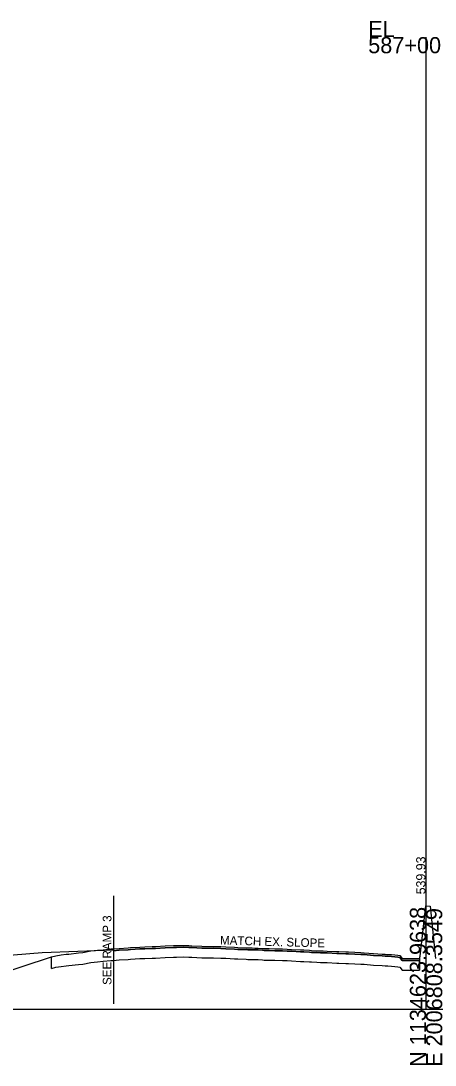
# Model space of a CAD drawing. Extents: x -201 to 2007062, y -213 to 1139737.
# Drawn here: x 1180 to 1251.6, y 2490.3 to 2671 of the extents above; entities that cross this region are included whole.
import ezdxf

# ---------------------------------------------------------------- set-up
doc = ezdxf.new("R2010")
doc.units = 0
for name, color, linetype in [('RD_DTM_Design_FG', 7, 'Continuous'), ('RD_GPK_XS_Cell', 7, 'Continuous'), ('RD_XS_ExGround', 7, 'Continuous'), ('RD_XS_ExPaveRet', 7, 'Continuous'), ('RD_XS_PaveOvlay', 7, 'Continuous'), ('RD_XS_SideStreet', 7, 'Continuous'), ('RD_XS_TX_Elev_EX', 7, 'Continuous'), ('RD_XS_TX_Slope', 7, 'Continuous')]:
    doc.layers.add(name, color=color, linetype=linetype)

msp = doc.modelspace()

# ---------------------------------------------------------------- linework, layer by layer
at = {"layer": 'RD_DTM_Design_FG'}
msp.add_lwpolyline([(1102.81, 2555.58), (1109.38, 2549), (1127.28, 2531.09), (1142.71, 2515.65), (1155.64, 2502.71), (1163.28, 2505.25), (1173.65, 2508.68), (1174.62, 2508.84), (1177.65, 2509.32), (1178.72, 2509.4), (1183.66, 2509.79), (1189.83, 2510.02), (1196, 2510.26)], dxfattribs=at)
at = {"layer": 'RD_GPK_XS_Cell'}
for p, q in [((1250, 2500), (1250, 2668.19)), ((1000, 2500), (1250, 2500)), ((1250, 2500), (1500, 2500))]:
    msp.add_line(p, q, dxfattribs=at)
at = {"layer": 'RD_XS_ExGround'}
msp.add_lwpolyline([(1174.91, 2505.63), (1185.26, 2509.03), (1186, 2509.24), (1186.93, 2509.37), (1187.79, 2509.48), (1188.27, 2509.53), (1189.91, 2509.73), (1190.7, 2509.79), (1192.05, 2510.06), (1193.21, 2510.18), (1194.22, 2510.28), (1195.54, 2510.41), (1195.86, 2510.42), (1196.97, 2510.51), (1198.54, 2510.61), (1198.92, 2510.63), (1200.52, 2510.73), (1201.4, 2510.76), (1202.64, 2510.82), (1203.24, 2510.84), (1204.92, 2510.93), (1206.37, 2511), (1206.89, 2511.01), (1208.02, 2511.03), (1209.01, 2510.99), (1209.51, 2510.97), (1211.25, 2510.89), (1213.25, 2510.85), (1214.53, 2510.81), (1215.37, 2510.79), (1216.91, 2510.7), (1217.49, 2510.67), (1218.91, 2510.62), (1219.21, 2510.61), (1219.62, 2510.59), (1219.92, 2510.58), (1220.39, 2510.57), (1221.01, 2510.56), (1221.74, 2510.51), (1222.04, 2510.49), (1222.91, 2510.47), (1223.86, 2510.44), (1225.18, 2510.41), (1225.98, 2510.38), (1226.74, 2510.33), (1228.31, 2510.26), (1228.9, 2510.23), (1229.88, 2510.17), (1230.22, 2510.15), (1231.11, 2510.11), (1231.76, 2510.09), (1232.22, 2510.06), (1232.89, 2510.05), (1234.58, 2509.96), (1234.9, 2509.95), (1236.15, 2509.91), (1236.59, 2509.89), (1237.71, 2509.85), (1238.71, 2509.79), (1239.28, 2509.75), (1240.9, 2509.62), (1242.41, 2509.53), (1242.95, 2509.49), (1243.37, 2509.46), (1244.01, 2509.44), (1244.63, 2509.38), (1245.1, 2509.31), (1245.45, 2509.25), (1245.85, 2508.73), (1248.3, 2508.76), (1248.88, 2508.74), (1249, 2509.18), (1249.98, 2517.87), (1250.74, 2517.83), (1251.64, 2508.76)], dxfattribs=at)
at = {"layer": 'RD_XS_ExPaveRet'}
for p, q in [((1196, 2510.1), (1196, 2508.43)), ((1185.26, 2507.03), (1185.26, 2509.03)), ((1190.7, 2507.79), (1192.05, 2508.06)), ((1192.05, 2508.06), (1193.21, 2508.18)), ((1193.21, 2508.18), (1194.22, 2508.28)), ((1194.22, 2508.28), (1195.54, 2508.41)), ((1195.54, 2508.41), (1195.86, 2508.42)), ((1195.86, 2508.42), (1196.97, 2508.51)), ((1196, 2508.43), (1196.97, 2508.51)), ((1196.97, 2508.51), (1198.54, 2508.61)), ((1196.97, 2508.51), (1198.54, 2508.61)), ((1198.54, 2508.61), (1198.92, 2508.63)), ((1198.54, 2508.61), (1198.92, 2508.63)), ((1198.92, 2508.63), (1200.52, 2508.73)), ((1198.92, 2508.63), (1200.52, 2508.73)), ((1200.52, 2508.73), (1201.4, 2508.76)), ((1200.52, 2508.73), (1201.4, 2508.76)), ((1201.4, 2508.76), (1202.64, 2508.82)), ((1201.4, 2508.76), (1202.64, 2508.82)), ((1202.64, 2508.82), (1203.24, 2508.84)), ((1202.64, 2508.82), (1203.24, 2508.84)), ((1203.24, 2508.84), (1204.92, 2508.93)), ((1203.24, 2508.84), (1204.92, 2508.93)), ((1204.92, 2508.93), (1206.37, 2509)), ((1204.92, 2508.93), (1206.37, 2509)), ((1206.37, 2509), (1206.89, 2509.01)), ((1206.37, 2509), (1206.89, 2509.01)), ((1206.89, 2509.01), (1208.02, 2509.03)), ((1206.89, 2509.01), (1208.02, 2509.03)), ((1208.02, 2509.03), (1209.01, 2508.99)), ((1208.02, 2509.03), (1209.01, 2508.99)), ((1209.01, 2508.99), (1209.51, 2508.97)), ((1209.01, 2508.99), (1209.51, 2508.97)), ((1209.51, 2508.97), (1211.25, 2508.89)), ((1209.51, 2508.97), (1211.25, 2508.89)), ((1211.25, 2508.89), (1213.25, 2508.85)), ((1211.25, 2508.89), (1213.25, 2508.85)), ((1213.25, 2508.85), (1214.53, 2508.81)), ((1213.25, 2508.85), (1214.53, 2508.81)), ((1214.53, 2508.81), (1215.37, 2508.79)), ((1214.53, 2508.81), (1215.37, 2508.79)), ((1215.37, 2508.79), (1216.91, 2508.7)), ((1215.37, 2508.79), (1216.91, 2508.7)), ((1216.91, 2508.7), (1217.49, 2508.67)), ((1216.91, 2508.7), (1217.49, 2508.67)), ((1217.49, 2508.67), (1218.91, 2508.62)), ((1217.49, 2508.67), (1218.91, 2508.62)), ((1218.91, 2508.62), (1219.21, 2508.61)), ((1218.91, 2508.62), (1219.21, 2508.61)), ((1219.21, 2508.61), (1219.62, 2508.59)), ((1219.21, 2508.61), (1219.62, 2508.59)), ((1219.62, 2508.59), (1219.92, 2508.58)), ((1219.62, 2508.59), (1219.92, 2508.58)), ((1219.92, 2508.58), (1220.39, 2508.57)), ((1219.92, 2508.58), (1220.39, 2508.57)), ((1220.39, 2508.57), (1221.01, 2508.56)), ((1220.39, 2508.57), (1221.01, 2508.56)), ((1221.01, 2508.56), (1221.74, 2508.51)), ((1221.01, 2508.56), (1221.74, 2508.51)), ((1221.74, 2508.51), (1222.04, 2508.49)), ((1221.74, 2508.51), (1222.04, 2508.49)), ((1222.04, 2508.49), (1222.91, 2508.47)), ((1222.04, 2508.49), (1222.91, 2508.47)), ((1222.91, 2508.47), (1223.86, 2508.44)), ((1222.91, 2508.47), (1223.86, 2508.44)), ((1223.86, 2508.44), (1225.18, 2508.41)), ((1223.86, 2508.44), (1225.18, 2508.41)), ((1225.18, 2508.41), (1225.98, 2508.38)), ((1225.18, 2508.41), (1225.98, 2508.38)), ((1225.98, 2508.38), (1226.74, 2508.33)), ((1225.98, 2508.38), (1226.74, 2508.33)), ((1226.74, 2508.33), (1228.31, 2508.26)), ((1226.74, 2508.33), (1228.31, 2508.26)), ((1228.31, 2508.26), (1228.9, 2508.23)), ((1228.31, 2508.26), (1228.9, 2508.23)), ((1228.9, 2508.23), (1229.88, 2508.17)), ((1228.9, 2508.23), (1229.88, 2508.17)), ((1229.88, 2508.17), (1230.22, 2508.15)), ((1229.88, 2508.17), (1230.22, 2508.15)), ((1230.22, 2508.15), (1231.11, 2508.11)), ((1230.22, 2508.15), (1231.11, 2508.11)), ((1231.11, 2508.11), (1231.76, 2508.09)), ((1231.11, 2508.11), (1231.76, 2508.09)), ((1231.76, 2508.09), (1232.22, 2508.06)), ((1231.76, 2508.09), (1232.22, 2508.06)), ((1232.22, 2508.06), (1232.89, 2508.05)), ((1232.22, 2508.06), (1232.89, 2508.05)), ((1232.89, 2508.05), (1234.58, 2507.96)), ((1232.89, 2508.05), (1234.58, 2507.96)), ((1234.58, 2507.96), (1234.9, 2507.95)), ((1234.58, 2507.96), (1234.9, 2507.95)), ((1234.9, 2507.95), (1236.15, 2507.91)), ((1234.9, 2507.95), (1236.15, 2507.91)), ((1236.15, 2507.91), (1236.59, 2507.89)), ((1236.15, 2507.91), (1236.59, 2507.89)), ((1236.59, 2507.89), (1237.71, 2507.85)), ((1236.59, 2507.89), (1237.71, 2507.85)), ((1248.88, 2508.74), (1248.88, 2506.74)), ((1248.88, 2506.74), (1248.88, 2508.41)), ((1185.26, 2507.03), (1186, 2507.24)), ((1186, 2507.24), (1186.93, 2507.37)), ((1186.93, 2507.37), (1187.79, 2507.48)), ((1187.79, 2507.48), (1188.27, 2507.53)), ((1188.27, 2507.53), (1189.91, 2507.73)), ((1189.91, 2507.73), (1190.7, 2507.79)), ((1237.71, 2507.85), (1238.71, 2507.79)), ((1237.71, 2507.85), (1238.71, 2507.79)), ((1238.71, 2507.79), (1239.28, 2507.75)), ((1238.71, 2507.79), (1239.28, 2507.75)), ((1239.28, 2507.75), (1240.9, 2507.62)), ((1239.28, 2507.75), (1240.9, 2507.62)), ((1240.9, 2507.62), (1242.41, 2507.53)), ((1240.9, 2507.62), (1242.41, 2507.53)), ((1242.41, 2507.53), (1242.95, 2507.49)), ((1242.41, 2507.53), (1242.95, 2507.49)), ((1242.95, 2507.49), (1243.37, 2507.46)), ((1242.95, 2507.49), (1243.37, 2507.46)), ((1243.37, 2507.46), (1244.01, 2507.44)), ((1243.37, 2507.46), (1244.01, 2507.44)), ((1244.01, 2507.44), (1244.63, 2507.38)), ((1244.01, 2507.44), (1244.63, 2507.38)), ((1244.63, 2507.38), (1245.1, 2507.31)), ((1244.63, 2507.38), (1245.1, 2507.31)), ((1245.1, 2507.31), (1245.45, 2507.25)), ((1245.1, 2507.31), (1245.45, 2507.25)), ((1245.45, 2507.25), (1245.85, 2506.73)), ((1245.45, 2507.25), (1245.85, 2506.73)), ((1245.85, 2506.73), (1248.3, 2506.76)), ((1245.85, 2506.73), (1248.3, 2506.76)), ((1248.3, 2506.76), (1248.88, 2506.74)), ((1248.3, 2506.76), (1248.88, 2506.74))]:
    msp.add_line(p, q, dxfattribs=at)
msp.add_lwpolyline([(1248.88, 2508.41), (1248.3, 2508.43), (1245.85, 2508.4), (1245.45, 2508.92), (1245.1, 2508.97), (1244.63, 2509.05), (1244.01, 2509.11), (1243.37, 2509.13), (1242.95, 2509.16), (1242.41, 2509.2), (1240.9, 2509.28), (1239.28, 2509.42), (1238.71, 2509.46), (1237.71, 2509.52), (1236.59, 2509.56), (1236.15, 2509.57), (1234.9, 2509.62), (1234.58, 2509.63), (1232.89, 2509.71), (1232.22, 2509.73), (1231.76, 2509.76), (1231.11, 2509.78), (1230.22, 2509.82), (1229.88, 2509.84), (1228.9, 2509.9), (1228.31, 2509.93), (1226.74, 2510), (1225.98, 2510.05), (1225.18, 2510.08), (1223.86, 2510.11), (1222.91, 2510.14), (1222.04, 2510.16), (1221.74, 2510.17), (1221.01, 2510.23), (1220.39, 2510.24), (1219.92, 2510.24), (1219.62, 2510.26), (1219.21, 2510.27), (1218.91, 2510.29), (1217.49, 2510.34), (1216.91, 2510.37), (1215.37, 2510.45), (1214.53, 2510.47), (1213.25, 2510.52), (1211.25, 2510.56), (1209.51, 2510.64), (1209.01, 2510.66), (1208.02, 2510.69), (1206.89, 2510.68), (1206.37, 2510.67), (1204.92, 2510.6), (1203.24, 2510.51), (1202.64, 2510.49), (1201.4, 2510.43), (1200.52, 2510.4), (1198.92, 2510.3), (1198.54, 2510.28), (1196.97, 2510.17), (1196, 2510.1)], dxfattribs=at)
at = {"layer": 'RD_XS_PaveOvlay'}
msp.add_line((1196, 2510.43), (1196, 2510.1), dxfattribs=at)
for points in [[(1196, 2510.43), (1196.97, 2510.51), (1198.54, 2510.61), (1198.92, 2510.63), (1200.52, 2510.73), (1201.4, 2510.76), (1202.64, 2510.82), (1203.24, 2510.84), (1204.92, 2510.93), (1206.37, 2511), (1206.89, 2511.01), (1208.02, 2511.03), (1209.01, 2510.99), (1209.51, 2510.97), (1211.25, 2510.89), (1213.25, 2510.85), (1214.53, 2510.81), (1215.37, 2510.79), (1216.91, 2510.7), (1217.49, 2510.67), (1218.91, 2510.62), (1219.21, 2510.61), (1219.62, 2510.59), (1219.92, 2510.58), (1220.39, 2510.57), (1221.01, 2510.56), (1221.74, 2510.51), (1222.04, 2510.49), (1222.91, 2510.47), (1223.86, 2510.44), (1225.18, 2510.41), (1225.98, 2510.38), (1226.74, 2510.33), (1228.31, 2510.26), (1228.9, 2510.23), (1229.88, 2510.17), (1230.22, 2510.15), (1231.11, 2510.11), (1231.76, 2510.09), (1232.22, 2510.06), (1232.89, 2510.05), (1234.58, 2509.96), (1234.9, 2509.95), (1236.15, 2509.91), (1236.59, 2509.89), (1237.71, 2509.85), (1238.71, 2509.79), (1239.28, 2509.75), (1240.9, 2509.62), (1242.41, 2509.53), (1242.95, 2509.49), (1243.37, 2509.46), (1244.01, 2509.44), (1244.63, 2509.38), (1245.1, 2509.31), (1245.45, 2509.25), (1245.85, 2508.73), (1248.3, 2508.76), (1248.88, 2508.74), (1248.88, 2508.74)], [(1196, 2510.1), (1196.97, 2510.17), (1198.54, 2510.28), (1198.92, 2510.3), (1200.52, 2510.4), (1201.4, 2510.43), (1202.64, 2510.49), (1203.24, 2510.51), (1204.92, 2510.6), (1206.37, 2510.67), (1206.89, 2510.68), (1208.02, 2510.69), (1209.01, 2510.66), (1209.51, 2510.64), (1211.25, 2510.56), (1213.25, 2510.52), (1214.53, 2510.47), (1215.37, 2510.45), (1216.91, 2510.37), (1217.49, 2510.34), (1218.91, 2510.29), (1219.21, 2510.27), (1219.62, 2510.26), (1219.92, 2510.24), (1220.39, 2510.24), (1221.01, 2510.23), (1221.74, 2510.17), (1222.04, 2510.16), (1222.91, 2510.14), (1223.86, 2510.11), (1225.18, 2510.08), (1225.98, 2510.05), (1226.74, 2510), (1228.31, 2509.93), (1228.9, 2509.9), (1229.88, 2509.84), (1230.22, 2509.82), (1231.11, 2509.78), (1231.76, 2509.76), (1232.22, 2509.73), (1232.89, 2509.71), (1234.58, 2509.63), (1234.9, 2509.62), (1236.15, 2509.57), (1236.59, 2509.56), (1237.71, 2509.52), (1238.71, 2509.46), (1239.28, 2509.42), (1240.9, 2509.28), (1242.41, 2509.2), (1242.95, 2509.16), (1243.37, 2509.13), (1244.01, 2509.11), (1244.63, 2509.05), (1245.1, 2508.97), (1245.45, 2508.92), (1245.85, 2508.4), (1248.3, 2508.43), (1248.88, 2508.41), (1248.88, 2508.41)]]:
    msp.add_lwpolyline(points, dxfattribs=at)
at = {"layer": 'RD_XS_SideStreet'}
msp.add_line((1196, 2519.59), (1196, 2500.91), dxfattribs=at)

# ---------------------------------------------------------------- texts
at = {"layer": 'RD_GPK_XS_Cell'}
for s, p in [('EL', (1240, 2668.19)), ('587+00.00 / 1', (1240, 2665.39))]:
    msp.add_text(s, height=2.8, dxfattribs=at).set_placement(p)
for s, p in [('N 1134623.9638', (1250, 2490)), ('E 2006808.3549', (1252.8, 2490))]:
    msp.add_text(s, height=2.8, rotation=90, dxfattribs=at).set_placement(p)
at = {"layer": 'RD_XS_SideStreet'}
msp.add_text('SEE RAMP 3', height=1.5, rotation=90, dxfattribs=at).set_placement((1195.62, 2504.18))
at = {"layer": 'RD_XS_TX_Elev_EX'}
msp.add_text('539.93', height=1.6, rotation=90, dxfattribs=at).set_placement((1249.9, 2519.86))
at = {"layer": 'RD_XS_TX_Slope'}
msp.add_text('MATCH EX. SLOPE', height=1.5, rotation=358.3671, dxfattribs=at).set_placement((1214.37, 2511.18))

doc.saveas('drawing.dxf')
